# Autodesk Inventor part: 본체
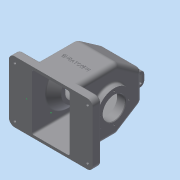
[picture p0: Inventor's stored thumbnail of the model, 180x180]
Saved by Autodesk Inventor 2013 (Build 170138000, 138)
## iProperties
Created: 2016-12
Part Number: 본체
Material: 일반
Document SubType Name: Modeling
Designer: Administrator
Density: 1 g/cm^3
Author: Administrator
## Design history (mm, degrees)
sketch "스케치4"
  geometry: L1 (65, -55)-(-65, -55); L2 (-75, -45)-(-75, 45); L3 (-65, 55)-(65, 55); L4 (75, 45)-(75, -45); L5 (75, -55)-(-75, 55); L6 (-75, -55)-(75, 55); A1 r 10 centre (65, -45) between (65, -55) and (75, -45); A2 r 10 centre (65, 45) between (75, 45) and (65, 55); A3 r 10 centre (-65, 45) between (-65, 55) and (-75, 45); A4 r 10 centre (-65, -45) between (-75, -45) and (-65, -55); 1 further point
  constraints: 12 end point, 8 point on circle, 8 point on line, 8 tangent, 4 centre point, 3 equal radius, 2 midpoint, 2 parallel, 1 horizontal, 1 perpendicular
  dimensions: "d4" = 150 distance of L5.start L6.start; "d6" = 110 distance of L6.start L5.end; "d7" = 10 radius of A1
sketch "스케치6"
  geometry: L1 (15, -55)-(0, -55) reference; L2 (0, -55)-(0, 55) reference; L3 (0, 55)-(15, 55) reference; L4 (15, 55)-(15, -55) reference; L5 (15, 55)-(81.402, 55); L6 (81.402, 55)-(125, 24.472); L7 (125, 24.472)-(125, -26.579); L8 (125, -26.579)-(80, -55); L9 (80, -55)-(15, -55); 1 further point
  constraints: 10 end point, 2 perpendicular, 1 equal length, 1 parallel
  dimensions: "d17" = 80 distance of L1.end L8.end; "d18" = 35 deg angle of L5 L6; "d19" = 125 distance between parallel lines of L2 L7
extrude "돌출2" join sketch "스케치6" stored distance "d20" = 77; taper "d21" = 0 deg
feature "쉘1" dims "d38" = 5
extrude "돌출5" join sketch "스케치4" distance "d39" = 15; taper "d40" = 0 deg
sketch "스케치13"
  geometry: L1 (-33.5, 15)-(33.5, 15) reference; L2 (33.5, 15)-(33.5, 120) reference; L3 (33.5, 120)-(-33.5, 120) reference; L4 (-33.5, 120)-(-33.5, 15) reference; L5 (75, 0)-(-75, 0) reference; L6 (-75, 0)-(-75, 15) reference; L7 (-75, 15)-(-38.5, 15) reference; L8 (-38.5, 15)-(-38.5, 125) reference; L9 (-38.5, 125)-(38.5, 125) reference; L10 (38.5, 125)-(38.5, 15) reference; L11 (38.5, 15)-(75, 15) reference; L12 (75, 15)-(75, 0) reference; L13 (-33.5, 15)-(-33.5, 0); L14 (33.5, 15)-(33.5, 0); 1 further point
  constraints: 4 end point, 2 perpendicular, 2 point on line
extrude "돌출6" cut sketch "스케치13" stored distance "d41" = 100; taper "d42" = 0 deg
sketch "스케치14"
  geometry: L1 (-65, 55)-(-38.5, 55) reference; L2 (-38.5, 55)-(38.5, 55) reference; L3 (38.5, 55)-(38.5, -55) reference; L4 (65, -55)-(38.5, -55) reference; L5 (75, 45)-(75, -45) reference; L6 (38.5, 55)-(65, 55) reference; L7 (-75, -45)-(-75, 45) reference; L8 (-38.5, -55)-(-65, -55) reference; L9 (38.5, -55)-(-38.5, -55) reference; L10 (-38.5, -55)-(-38.5, 55) reference; L11 (-38.5, 55)-(-38.5, -55) reference; L12 (-38.5, 55)-(-65, 55) reference; L13 (-75, 45)-(-75, -45) reference; L14 (-65, -55)-(-38.5, -55) reference; L15 (38.5, -55)-(38.5, 55) reference; L16 (38.5, -55)-(65, -55) reference; L17 (75, -45)-(75, 45) reference; L18 (65, 55)-(38.5, 55) reference; L19 (-33.5, 50)-(-33.5, -50) reference; L20 (-33.5, -50)-(33.5, -50) reference; L21 (33.5, -50)-(33.5, 50) reference; L22 (33.5, 50)-(-33.5, 50) reference; A1 r 10 centre (65, -45) between (65, -55) and (75, -45) reference; A2 r 10 centre (65, 45) between (75, 45) and (65, 55) reference; A3 r 10 centre (-65, 45) between (-65, 55) and (-75, 45) reference; A4 r 10 centre (-65, -45) between (-75, -45) and (-65, -55) reference; A5 r 10 centre (-65, 45) between (-65, 55) and (-75, 45) reference; A6 r 10 centre (-65, -45) between (-75, -45) and (-65, -55) reference; A7 r 10 centre (65, -45) between (65, -55) and (75, -45) reference; A8 r 10 centre (65, 45) between (75, 45) and (65, 55) reference; 5 further points
  constraints: 4 coincident
hole "구멍2" sketch "스케치14" at (-65, 45), (65, 45), (65, -45), (-65, -45) diameter "d43" = 5; stored, may be unused: countersink angle "d47" = 90 deg, drill point angle "d49" = 118 deg; dims "d44" = 6, "d45" = 12, "d46" = 5, "d48" = 8
sketch "스케치15"
  geometry: L1 (-73.148, 65)-(76.59, 65); L2 (45, 0)-(-45, 0) reference; L3 (-55, 80)-(-55, 15) reference; L4 (-55, 15)-(55, 15) reference; L5 (55, 15)-(55, 81.402) reference; L6 (55, 81.402)-(24.472, 125) reference; L7 (24.472, 125)-(-26.579, 125) reference; L8 (-26.579, 125)-(-55, 80) reference; L9 (-1.053, 125)-(-1.053, -16.719); C1 r 37.5 at (-1.053, 65); C2 r 29 at (-1.053, 65); C3 r 20 at (-1.053, 65); 1 further point
  constraints: 4 end point, 3 centre point, 2 coincident, 2 point on line, 1 horizontal, 1 midpoint, 1 perpendicular
  dimensions: "d50" = 65 distance between parallel lines of L2 L1; "d51" = 75 diameter of C1; "d52" = 58 diameter of C2; "d53" = 40 diameter of C3
  node "투영된 루프6"
extrude "돌출7" join sketch "스케치15" distance "d58" = 5; taper "d59" = 0 deg
sketch "스케치19"
  geometry: L1 (-33.5, 0)-(-75, 0) reference; L2 (-75, 0)-(-75, 15) reference; L3 (-75, 15)-(-38.5, 15) reference; L4 (-38.5, 15)-(-38.5, 27.515) reference; L5 (-38.5, 27.515)-(-43.5, 27.515) reference; L6 (-43.5, 27.515)-(-43.5, 102.485) reference; L7 (-43.5, 102.485)-(-38.5, 102.485) reference; L8 (-38.5, 102.485)-(-38.5, 125) reference; L9 (-38.5, 125)-(38.5, 125) reference; L10 (38.5, 125)-(38.5, 15) reference; L11 (38.5, 15)-(75, 15) reference; L12 (75, 15)-(75, 0) reference; L13 (75, 0)-(33.5, 0) reference; L14 (33.5, 0)-(33.5, 120) reference; L15 (33.5, 120)-(-33.5, 120) reference; L16 (-33.5, 120)-(-33.5, 0) reference; L17 (-56.75, 65)-(60.02, 65); L18 (33.5, 0)-(-33.5, 0) reference; L19 (-33.5, 106)-(-19.5, 92); L20 (-19.5, 92)-(-19.5, 65); L21 (-33.5, 106)-(-33.5, 65); 1 further point
  constraints: 8 end point, 4 point on line, 2 perpendicular
  dimensions: "d61" = 65 distance between parallel lines of L18 L17; "d62" = 45 deg angle of L20 L19; "d63" = 54 diameter of L19.end L17; "d64" = 24 distance between parallel lines of L20 L6
revolve "회전1" sketch "스케치19" stored, may be unused: angle "d65" = 90 deg
sketch "스케치20"
  geometry: L1 (-77.082, 65)-(75.36, 65); L2 (55, 15)-(55, 80) reference; L3 (55, 80)-(26.579, 125) reference; L4 (26.579, 125)-(-24.472, 125) reference; L5 (-24.472, 125)-(-55, 81.402) reference; L6 (-55, 81.402)-(-55, 15) reference; L7 (-55, 15)-(55, 15) reference; L8 (45, 0)-(-45, 0) reference; L9 (1.053, 125)-(1.053, -17.949); C1 r 31 at (1.053, 65); C2 r 26 at (1.053, 65); 1 further point
  constraints: 4 end point, 2 centre point, 2 point on line, 1 coincident, 1 horizontal, 1 midpoint, 1 perpendicular
  dimensions: "d66" = 65 distance between parallel lines of L8 L1; "d67" = 62 diameter of C1; "d68" = 52 diameter of C2
extrude "돌출8" join sketch "스케치20" distance "d69" = 10; taper "d70" = 0 deg
extrude "돌출9" cut sketch "스케치15" stored distance "d71" = 10; taper "d72" = 0 deg
sketch "스케치21"
  geometry: 1 further point
sketch "스케치22" dims "d73" = 58
  geometry: C1 r 37.5 at (0, 0) reference; 3 further points
  constraints: 2 vertical alignment, 1 coincident, 2 other
hole "구멍3" sketch "스케치22" at (0, 29) diameter "d75" = 2.459; stored, may be unused: countersink angle "d79" = 90 deg, drill point angle "d81" = 118 deg; dims "d76" = 6, "d77" = 12, "d78" = 5, "d80" = 8
sketch "스케치23" dims "d85" = 52
  geometry: C1 r 31 at (0, 0) reference; 3 further points
  constraints: 2 vertical alignment, 1 coincident, 2 other
hole "구멍4" sketch "스케치23" at (0, 26) diameter "d87" = 2.459; stored, may be unused: countersink angle "d91" = 90 deg, drill point angle "d93" = 118 deg; dims "d88" = 6, "d89" = 12, "d90" = 5, "d92" = 8
node "작업 평면2"
sketch "스케치24"
  geometry: L1 (38.5, 24.472)-(-38.5, 24.472) reference; L2 (-38.5, -26.579)-(-38.5, 24.472) reference; L3 (38.5, -26.579)-(-38.5, -26.579) reference; L4 (38.5, 24.472)-(38.5, -26.579) reference; L5 (24.333, -13.553)-(16.333, -13.553); L6 (16.333, -13.553)-(16.333, 11.447); L7 (16.333, 11.447)-(24.333, 11.447); L8 (24.333, 11.447)-(24.333, -13.553); L9 (-19.667, -13.553)-(-27.667, -13.553); L10 (-27.667, -13.553)-(-27.667, 11.447); L11 (-27.667, 11.447)-(-19.667, 11.447); L12 (-19.667, 11.447)-(-19.667, -13.553); L13 (-38.5, -26.579)-(-38.5, 24.472) reference; L14 (38.5, -1.053)-(-56.15, -1.053); 7 further points
  constraints: 18 end point, 7 midpoint, 4 horizontal alignment, 4 parallel, 3 perpendicular, 2 horizontal, 1 collinear
  dimensions: "d98" = 36 distance between parallel lines of L12 L6; "d100" = 52 distance between parallel lines of L10 L8; "d101" = 25 distance of L5.end L6.end; "d102" = 25 distance of L11.end L9.start
extrude "돌출10" join sketch "스케치24" stored distance "d103" = 10; taper "d104" = 0 deg
sketch "스케치25"
  geometry: L1 (25, -15)-(0, -15) reference; L2 (25, 0)-(25, -15) reference; L3 (25, 0)-(0, 0) reference; L4 (0, 0)-(0, -15) reference; L5 (5, -5)-(20, -5); L6 (20, -5)-(20, -15); L7 (20, -15)-(5, -15); L8 (5, -15)-(5, -5); 3 further points
  constraints: 8 end point, 2 midpoint, 2 parallel, 1 horizontal, 1 perpendicular, 1 point on line, 1 vertical alignment
  dimensions: "d106" = 5 distance between parallel lines of L5 L3; "d107" = 15 distance of L5.start L5.end
extrude "돌출11" cut sketch "스케치25" stored distance "d108" = 10; taper "d109" = 0 deg
sketch "스케치26"
  geometry: L1 (77, 0)-(77, -66.402) reference; L2 (0, 0)-(77, 0) reference; L3 (0, -66.402)-(0, 0) reference; L4 (-26.5, -66.402)-(0, -66.402) reference; L5 (-26.5, -81.402)-(-26.5, -66.402) reference; L6 (103.5, -81.402)-(-26.5, -81.402) reference; L7 (103.5, -81.402)-(103.5, -66.402) reference; L8 (77, -66.402)-(103.5, -66.402) reference; 2 further points
  constraints: 1 other
  dimensions: "d110" = 38.5 distance from line of L3 point (38.5, -36.402); "d111" = 45 distance from line of L6 point (38.5, -36.402)
feature "엠보싱1" sketch "스케치26" dims "d4" = 150, "d6" = 110, "d7" = 10, "d112" = 0.5, "d113" = 0
fillet "모깎기1" dims "d114" = 10, "d115" = 8
fillet "모깎기2" dims "d116" = 8
fillet "모깎기3" dims "d117" = 1
fillet "모깎기4" dims "d118" = 8
chamfer "모따기1" distance "d119" = 1; stored, may be unused: second distance "d120" = 2, angle "d121" = 45 deg
fillet "모깎기5" dims "d122" = 3
fillet "모깎기6" dims "d123" = 3
sketch "스케치27"
  geometry: 1 further point
fillet "모깎기7" dims "d124" = 1
fillet "모깎기8" dims "d125" = 1
node "솔리드1"
pattern_circular "원형 패턴1" dims angle "d83" = 360 deg
pattern_circular "원형 패턴2" dims angle "d95" = 360 deg
node "투영된 루프4"
node "투영된 루프5"
node "투영된 루프7"
node "투영된 루프8"
node "투영된 루프9"
node "투영된 루프10"
node "절단 모서리 투영1"
node "절단 모서리 투영3"
node "절단 모서리 투영4"
node "절단 모서리 투영6"
